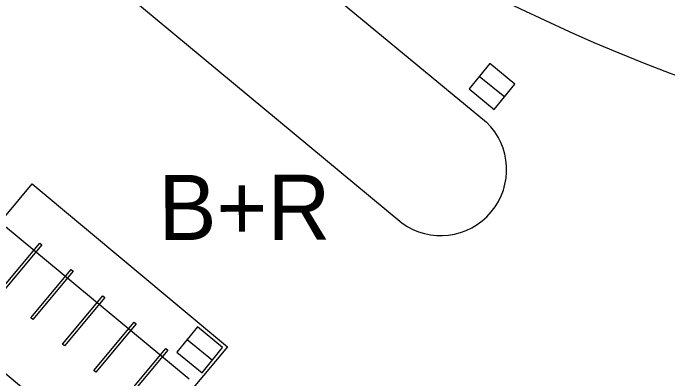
# Model space of a CAD drawing. Extents: x -438303 to -437792, y -1133191 to -1132731.
# Drawn here: x -438077.75 to -438067.71, y -1132981.97 to -1132976.36 of the extents above; entities that cross this region are included whole.
import ezdxf

# ---------------------------------------------------------------- set-up
doc = ezdxf.new("R2010")
doc.units = 0
for name, color, linetype in [('Default', 7, 'Continuous'), ('MOBILIÁŘ', 7, 'Continuous'), ('Vrstva 1', 7, 'Continuous'), ('Vrstva 10', 7, 'Continuous'), ('Vrstva 27', 7, 'Continuous')]:
    doc.layers.add(name, color=color, linetype=linetype)

# ---------------------------------------------------------------- blocks, each defined once
blk = doc.blocks.new('A$C73EC33FB')
at = {"layer": 'Default'}
for points in [[(-39000, 25012), (0, 25012), (0, 0), (-39000, 0)], [(-32310, 18759), (-31900, 18759), (-31900, 9105), (-32310, 9105)], [(-26014, 18759), (-25605, 18759), (-25605, 9105), (-26014, 9105)], [(-19705, 18759), (-19295, 18759), (-19295, 9105), (-19705, 9105)], [(-13409, 18759), (-13000, 18759), (-13000, 9105), (-13409, 9105)], [(-7100, 18759), (-6690, 18759), (-6690, 9105), (-7100, 9105)]]:
    blk.add_lwpolyline(points, close=True, dxfattribs=at)

msp = doc.modelspace()

# ---------------------------------------------------------------- linework, layer by layer
at = {"layer": 'Vrstva 1'}
for p, q in [((-438070.407, -1132977.489), (-438070.407, -1132977.489)), ((-438070.491, -1132978.033), (-438070.491, -1132978.033)), ((-438070.385, -1132979.368), (-438070.385, -1132979.368)), ((-438071.79, -1132979.58), (-438071.79, -1132979.58)), ((-438074.89, -1132981.527), (-438074.89, -1132981.527)), ((-438075.049, -1132981.974), (-438075.049, -1132981.974))]:
    msp.add_line(p, q, dxfattribs=at)
msp.add_arc((-438057.911, -1132951.468), 27.6, 199.6428, 254.4643, dxfattribs=at)
msp.add_arc((-438057.911, -1132951.468), 27.6, 199.6428, 254.4643, dxfattribs=at)
at = {"layer": 'Vrstva 10'}
for points in [[(-438086.852, -1132964.524), (-438070.491, -1132978.033)], [(-438088.005, -1132966.118), (-438071.79, -1132979.58)], [(-438091.119, -1132968.638), (-438075.049, -1132981.974)]]:
    msp.add_lwpolyline(points, dxfattribs=at)
msp.add_arc((-438071.196, -1132978.761), 1.013, 234.0231, 45.9423, dxfattribs=at)
at = {"layer": 'Vrstva 27'}
for p, q in [((-438070.602, -1132977.331), (-438070.213, -1132977.646)), ((-438075.084, -1132981.369), (-438074.696, -1132981.685))]:
    msp.add_line(p, q, dxfattribs=at)
for points in [[(-438070.759, -1132977.524), (-438070.372, -1132977.841), (-438070.055, -1132977.453), (-438070.443, -1132977.137)], [(-438075.242, -1132981.563), (-438074.854, -1132981.879), (-438074.538, -1132981.491), (-438074.926, -1132981.175)]]:
    msp.add_lwpolyline(points, close=True, dxfattribs=at)

# ---------------------------------------------------------------- block references
at = {"layer": 'MOBILIÁŘ', "xscale": 0.00010000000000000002, "yscale": 0.00010000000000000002, "rotation": -39.862018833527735}
msp.add_blockref('A$C73EC33FB', (-438076.066, -1132983.402), dxfattribs=at)
msp.add_blockref('A$C73EC33FB', (-438076.066, -1132983.402), dxfattribs=at)

# ---------------------------------------------------------------- texts
at = {"layer": 'Vrstva 1'}
msp.add_text('B+R', height=1, rotation=0.1042, dxfattribs=at).set_placement((-438075.523, -1132979.844))
msp.add_text('B+R', height=1, rotation=0.1042, dxfattribs=at).set_placement((-438075.523, -1132979.844))

doc.saveas('drawing.dxf')
